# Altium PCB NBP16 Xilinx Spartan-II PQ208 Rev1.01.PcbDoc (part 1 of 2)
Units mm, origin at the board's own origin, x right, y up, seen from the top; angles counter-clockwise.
Board outline 69 x 80.99 mm, 2 copper layers (Top Layer, Bottom Layer); 48 components, 186 nets, 518 pads, 188 vias.
Unrouted connection lines stored in the file: 1.
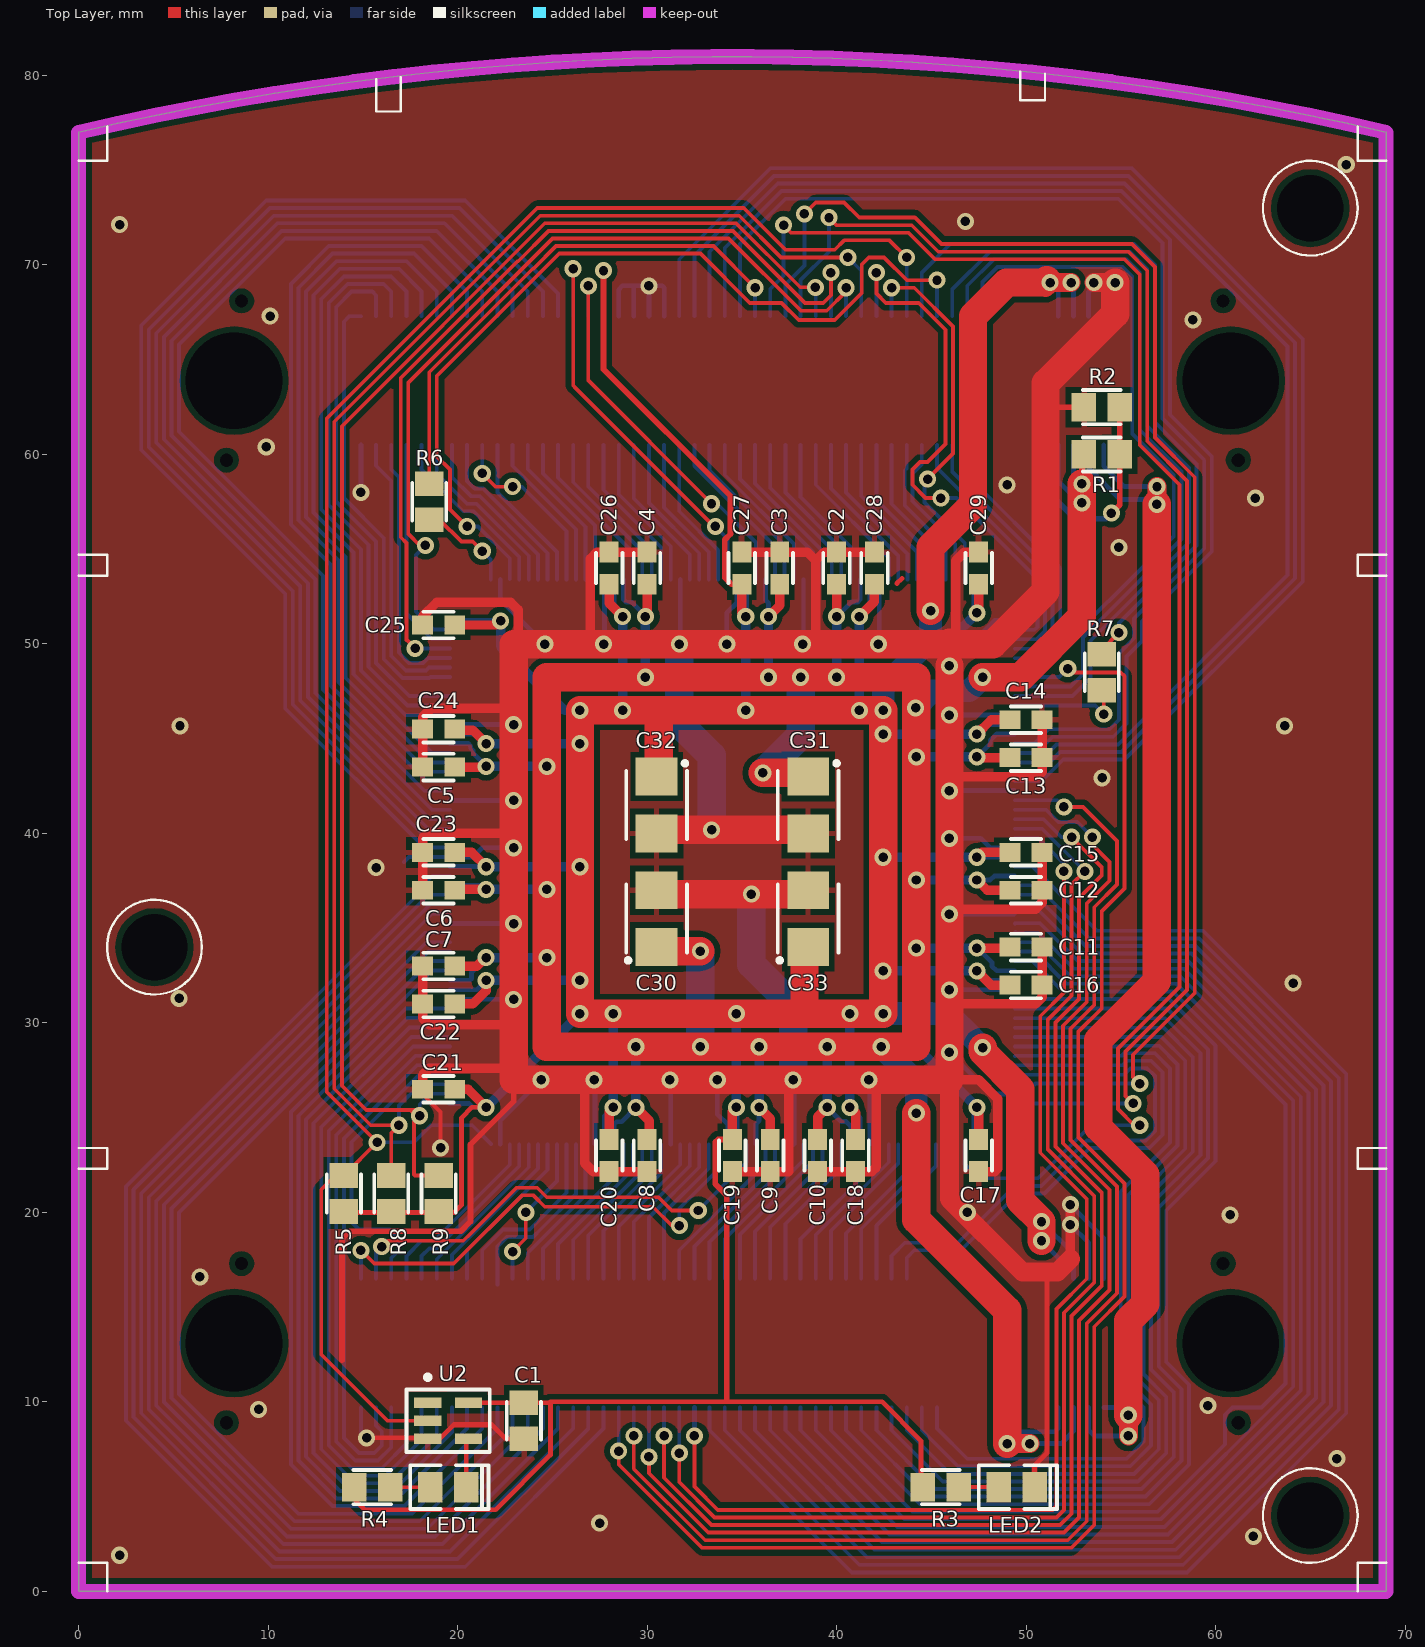
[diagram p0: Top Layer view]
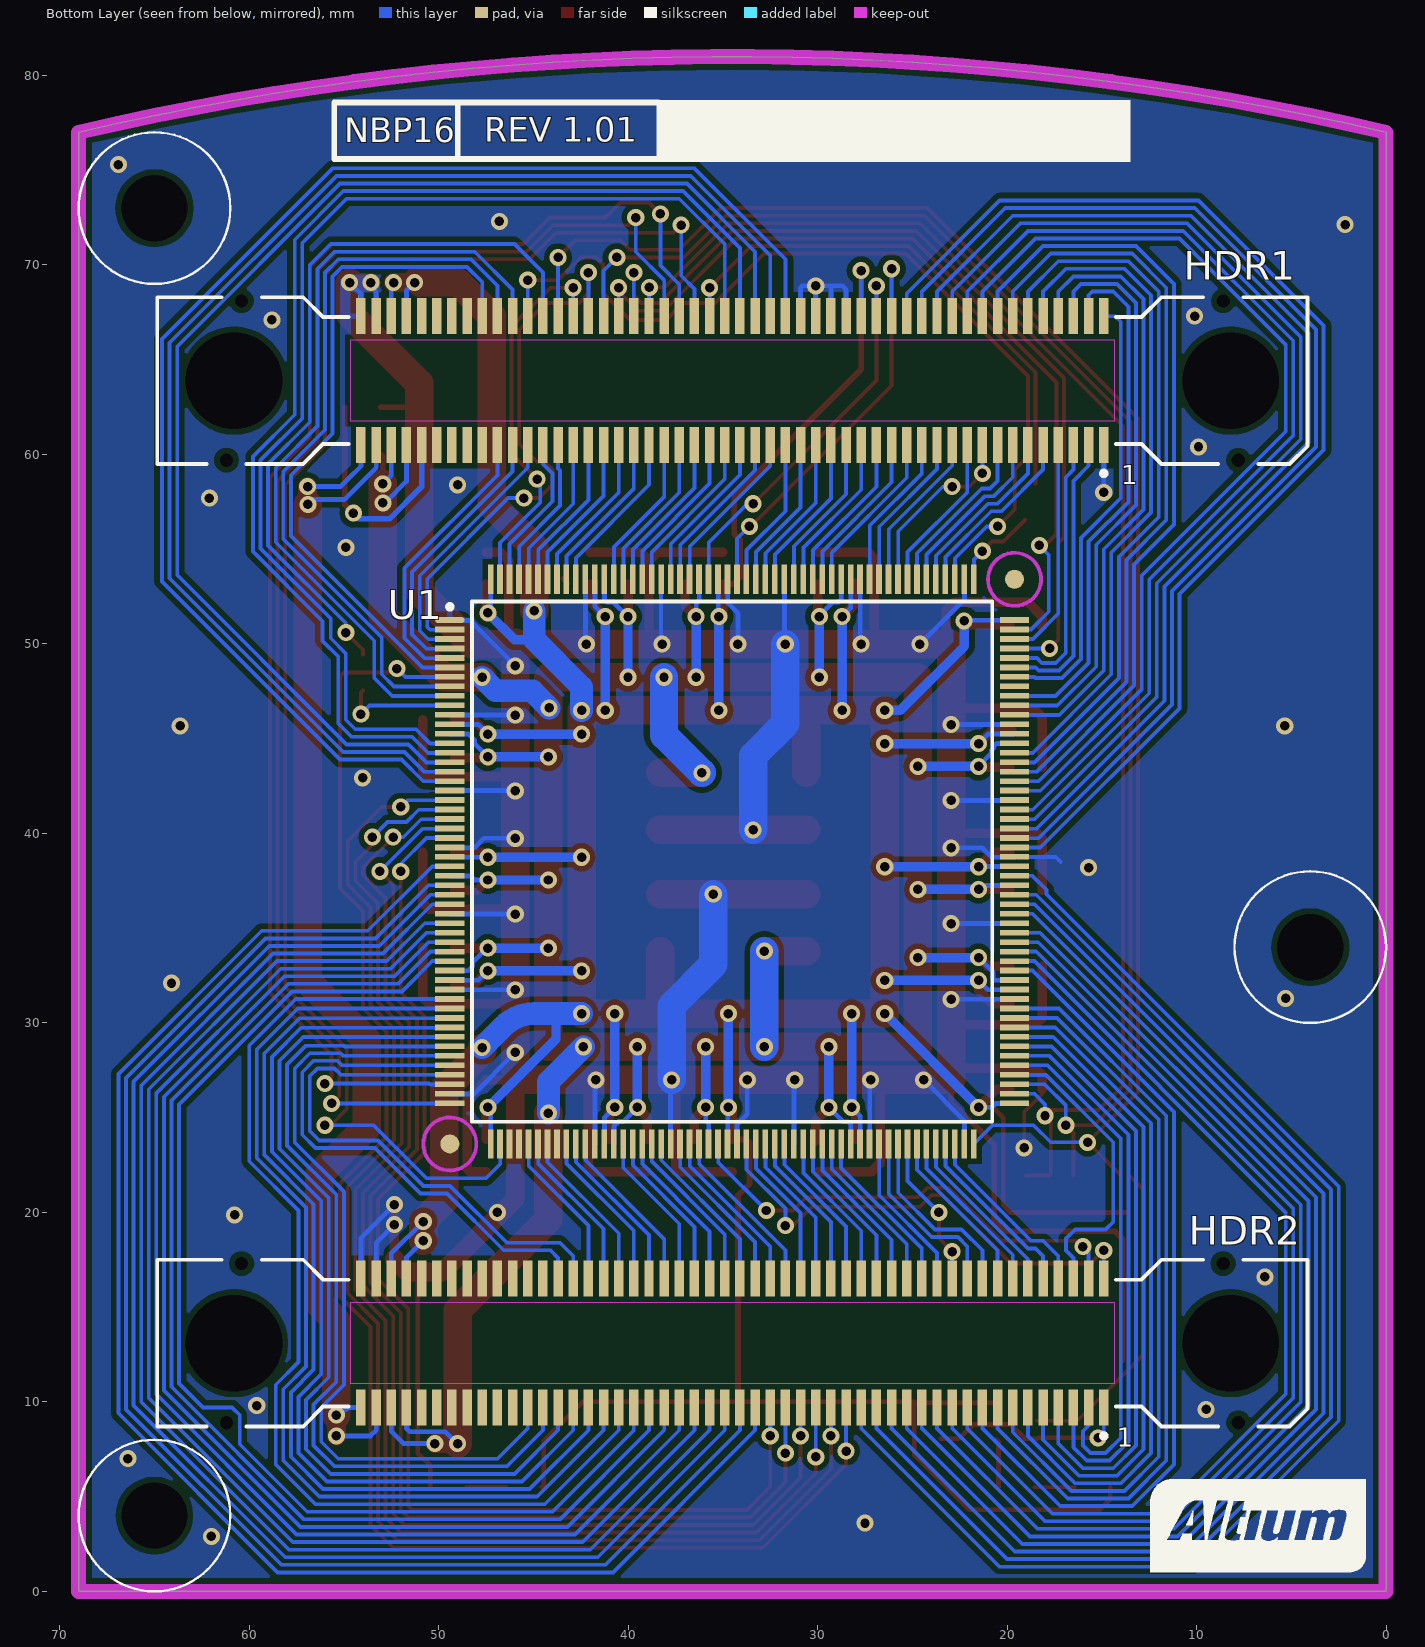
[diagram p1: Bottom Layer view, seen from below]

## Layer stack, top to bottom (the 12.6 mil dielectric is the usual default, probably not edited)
Top Layer: signal copper 0.0356
Dielectric: core 0.32, FR-4, Dk 4.8
Bottom Layer: signal copper 0.0356

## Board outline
0,0 0.001,77 cw(c34.5,-69.801) 69,77 69,0

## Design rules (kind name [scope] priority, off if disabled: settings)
Clearance Clearance_Polygons [InPolygon] p1: gap=0.3
Clearance [All] p2: gap=0.2
ComponentClearance [All] p1: gap=0.2 collisioncheckmode=3 verticalgap=0.254 showdistances=FALSE
FabricationTestPointUsage TestPointUsage [All] p1 off: valid=0 allowmultiple=FALSE
FabricationTestpoint Testpoint [All] p1 off: side=3 testpointundercomponent=TRUE minsize=1.016 maxsize=2.54 preferedsize=1.524 minholesize=0 maxholesize=1.016 preferedholesize=0.813 testpointgrid=0.025 allowsidetop=TRUE allowsidebottom=TRUE usegrid=TRUE gridtolerance=0
HoleSize [All] p1: absolutevalues=TRUE maxlimit=5.2 minlimit=0.25 maxpercent=80.000 minpercent=20.000
PlaneClearance [All] p1: clearance=0.5
PlaneConnect PlaneConnect_Vias [IsVia] p1: planeconnectstyle=Direct reliefexpansion=0.508 reliefentries=4 reliefconductorwidth=0.254 reliefairgap=0.254
PlaneConnect [All] p2: planeconnectstyle=Relief reliefexpansion=0.5 reliefentries=4 reliefconductorwidth=0.25 reliefairgap=0.25
PolygonConnect [All] p1: connectstyle=Relief reliefconductorwidth=0.3 reliefentries=4 polygonreliefangle="90 Angle"
RoomDefinition BOCD_SpartanII_PQ208 [InComponentClass('BOCD_SpartanII_PQ208')] p1 off: confinementstyle=ConfineIn formatcopy=TRUE lockcomponents=FALSE outline 3.7,3.8 65.3,3.8 65.3,68.8 3.7,68.8
RoutingVias [All] p1: holewidth=0.5 width=0.9 viastyle="Through Hole" minholewidth=0.3 minwidth=0.6 maxholewidth=0.5 maxwidth=0.9
SMDNeckDown [All] p1: percent=100.000
SilkscreenOverComponentPads [All] p1: minsilkscreentomaskgap=0.254
SolderMaskExpansion SolderMaskExpansion_Vias [IsVia] p1: expansion=-0.2
SolderMaskExpansion [All] p2: expansion=0.1
Width [All] p1: maxlimit=1.5 minlimit=0.2 preferedwidth=0.25
21 further rules are at their usual default settings.

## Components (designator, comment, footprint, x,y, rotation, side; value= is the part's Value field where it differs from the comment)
C1 "0.1uF" CC2012-0805 23.5,9 r90 top
C2 "0.1uF" CC1608-0603 40,54 r90 top
C3 "0.1uF" CC1608-0603 37,54 r90 top
C4 "0.1uF" CC1608-0603 30,54 r90 top
C5 "0.1uF" CC1608-0603 19,43.5 r180 top
C6 "0.1uF" CC1608-0603 19,37 r180 top
C7 "0.1uF" CC1608-0603 19,33 r180 top
C8 "0.1uF" CC1608-0603 30,23 r270 top
C9 "0.1uF" CC1608-0603 36.5,23 r270 top
C10 "0.1uF" CC1608-0603 39,23 r270 top
C11 "0.1uF" CC1608-0603 50,34 r0 top
C12 "0.1uF" CC1608-0603 50,37 r0 top
C13 "0.1uF" CC1608-0603 50,44 r0 top
C14 "0.1uF" CC1608-0603 50,46 r0 top
C15 "0.1uF" CC1608-0603 50,39 r0 top
C16 "0.1uF" CC1608-0603 50,32 r0 top
C17 "0.1uF" CC1608-0603 47.5,23 r90 top
C18 "0.1uF" CC1608-0603 41,23 r90 top
C19 "0.1uF" CC1608-0603 34.5,23 r90 top
C20 "0.1uF" CC1608-0603 28,23 r90 top
C21 "0.1uF" CC1608-0603 19,26.5 r0 top
C22 "0.1uF" CC1608-0603 19,31 r180 top
C23 "0.1uF" CC1608-0603 19,39 r180 top
C24 "0.1uF" CC1608-0603 19,45.5 r180 top
C25 "0.1uF" CC1608-0603 19,51 r0 top
C26 "0.1uF" CC1608-0603 28,54 r270 top
C27 "0.1uF" CC1608-0603 35,54 r270 top
C28 "0.1uF" CC1608-0603 42,54 r270 top
C29 "0.1uF" CC1608-0603 47.5,54 r270 top
C30 "10uF TANT" MCCT-B 30.5,35.5 r90 top
C31 "10uF TANT" MCCT-B 38.5,41.5 r270 top
C32 "10uF TANT" MCCT-B 30.5,41.5 r270 top
C33 "10uF TANT" MCCT-B 38.5,35.5 r90 top
HDR1 "54075-1009" 54075 34.5,63.9 r0 bottom locked
HDR2 "54075-1009" 54075 34.5,13.1 r0 bottom locked
LED1 "HSMG-C170" "SMD _LED" 19.5,5.5 r180 top locked
LED2 "HSMH-C170" "SMD _LED" 49.5,5.5 r180 top locked
R1 "82R 1%" CC2012-0805 54,60 r0 top
R2 "680R 1%" CC2012-0805 54,62.5 r180 top
R3 "270R" CC2012-0805 45.5,5.5 r0 top
R4 "270R" CC2012-0805 15.5,5.5 r180 top
R5 "4K7" CC2012-0805 14,21 r90 top
R6 "100R" CC2012-0805 18.5,57.5 r270 top
R7 "100R" CC2012-0805 54,48.5 r90 top
R8 "4K7" CC2012-0805 16.5,21 r90 top
R9 "4K7" CC2012-0805 19,21 r90 top
U1 "XC2S200-6PQ208C" F-QFP28X28-G208/P.5N 34.5,38.5 r180 bottom locked
U2 "SN74LVC1G04DBV" SO-G5/P.95 19.5,9 r270 top

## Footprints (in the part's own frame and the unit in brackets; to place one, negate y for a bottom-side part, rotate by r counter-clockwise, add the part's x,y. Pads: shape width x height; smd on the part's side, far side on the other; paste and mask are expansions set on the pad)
54075 [mm] "Connector; Docking Station, Receptacle; 100 Position; Vertical"
  rect 0.5x1.9 smd: 1(-19.6,3.4) 2(-19.6,-3.4) 3(-18.8,3.4) 4(-18.8,-3.4) 5(-18,3.4) 6(-18,-3.4) 7(-17.2,3.4) 8(-17.2,-3.4) 9(-16.4,3.4) 10(-16.4,-3.4) 11(-15.6,3.4) 12(-15.6,-3.4) 13(-14.8,3.4) 14(-14.8,-3.4) 15(-14,3.4) 16(-14,-3.4) 17(-13.2,3.4) 18(-13.2,-3.4) 19(-12.4,3.4) 20(-12.4,-3.4) 21(-11.6,3.4) 22(-11.6,-3.4) 23(-10.8,3.4) 24(-10.8,-3.4) 25(-10,3.4) 26(-10,-3.4) 27(-9.2,3.4) 28(-9.2,-3.4) 29(-8.4,3.4) 30(-8.4,-3.4) 31(-7.6,3.4) 32(-7.6,-3.4) 33(-6.8,3.4) 34(-6.8,-3.4) 35(-6,3.4) 36(-6,-3.4) 37(-5.2,3.4) 38(-5.2,-3.4) 39(-4.4,3.4) 40(-4.4,-3.4) 41(-3.6,3.4) 42(-3.6,-3.4) 43(-2.8,3.4) 44(-2.8,-3.4) 45(-2,3.4) 46(-2,-3.4) 47(-1.2,3.4) 48(-1.2,-3.4) 49(-0.4,3.4) 50(-0.4,-3.4) 51(0.4,3.4) 52(0.4,-3.4) 53(1.2,3.4) 54(1.2,-3.4) 55(2,3.4) 56(2,-3.4) 57(2.8,3.4) 58(2.8,-3.4) 59(3.6,3.4) 60(3.6,-3.4) 61(4.4,3.4) 62(4.4,-3.4) 63(5.2,3.4) 64(5.2,-3.4) 65(6,3.4) 66(6,-3.4) 67(6.8,3.4) 68(6.8,-3.4) 69(7.6,3.4) 70(7.6,-3.4) 71(8.4,3.4) 72(8.4,-3.4) 73(9.2,3.4) 74(9.2,-3.4) 75(10,3.4) 76(10,-3.4) 77(10.8,3.4) 78(10.8,-3.4) 79(11.6,3.4) 80(11.6,-3.4) 81(12.4,3.4) 82(12.4,-3.4) 83(13.2,3.4) 84(13.2,-3.4) 85(14,3.4) 86(14,-3.4) 87(14.8,3.4) 88(14.8,-3.4) 89(15.6,3.4) 90(15.6,-3.4) 91(16.4,3.4) 92(16.4,-3.4) 93(17.2,3.4) 94(17.2,-3.4) 95(18,3.4) 96(18,-3.4) 97(18.8,3.4) 98(18.8,-3.4) 99(19.6,3.4) 100(19.6,-3.4)
  round 0.5 hole 0.7 unplated: MH1(-26.7,4.2) MH2(-25.9,-4.2) MH3(26.7,4.2) MH4(25.9,-4.2)
  round 4.8 hole 5.1 unplated: MH5(-26.3,0) MH6(26.3,0)
  Top Layer keep-out region: -20.15,2.15 20.15,2.15 20.15,-2.15 -20.15,-2.15
  silkscreen extent -30.35,-4.4 30.35,5.02
CC1608-0603 [mm]
  rect 1.1x1 smd: 1(-0.85,0) 2(0.85,0)
  silkscreen extent -0.8,-0.7 0.8,0.7
CC2012-0805 [mm]
  rect 1.3x1.5 smd: 1(-0.95,0.003) 2(0.95,0.003)
  silkscreen extent -1,-0.9 1,0.9
F-QFP28X28-G208/P.5N [mm]
  oval 1.55x0.3 smd: 1(-14.91,12.761)
  rect 1.55x0.3 smd: 2(-14.91,12.261) 3(-14.91,11.761) 4(-14.91,11.261) 5(-14.91,10.761) 6(-14.91,10.261) 7(-14.91,9.761) 8(-14.91,9.261) 9(-14.91,8.761) 10(-14.91,8.261) 11(-14.91,7.761) 12(-14.91,7.261) 13(-14.91,6.761) 14(-14.91,6.261) 15(-14.91,5.761) 16(-14.91,5.261) 17(-14.91,4.761) 18(-14.91,4.261) 19(-14.91,3.761) 20(-14.91,3.261) 21(-14.91,2.761) 22(-14.91,2.261) 23(-14.91,1.761) 24(-14.91,1.261) 25(-14.91,0.761) 26(-14.91,0.261) 27(-14.91,-0.239) 28(-14.91,-0.739) 29(-14.91,-1.239) 30(-14.91,-1.739) 31(-14.91,-2.239) 32(-14.91,-2.739) 33(-14.91,-3.239) 34(-14.91,-3.739) 35(-14.91,-4.239) 36(-14.91,-4.739) 37(-14.91,-5.239) 38(-14.91,-5.739) 39(-14.91,-6.239) 40(-14.91,-6.739) 41(-14.91,-7.239) 42(-14.91,-7.739) 43(-14.91,-8.239) 44(-14.91,-8.739) 45(-14.91,-9.239) 46(-14.91,-9.739) 47(-14.91,-10.239) 48(-14.91,-10.739) 49(-14.91,-11.239) 50(-14.91,-11.739) 51(-14.91,-12.239) 52(-14.91,-12.739) 105(14.89,-12.739) 106(14.89,-12.239) 107(14.89,-11.739) 108(14.89,-11.239) 109(14.89,-10.739) 110(14.89,-10.239) 111(14.89,-9.739) 112(14.89,-9.239) 113(14.89,-8.739) 114(14.89,-8.239) 115(14.89,-7.739) 116(14.89,-7.239) 117(14.89,-6.739) 118(14.89,-6.239) 119(14.89,-5.739) 120(14.89,-5.239) 121(14.89,-4.739) 122(14.89,-4.239) 123(14.89,-3.739) 124(14.89,-3.239) 125(14.89,-2.739) 126(14.89,-2.239) 127(14.89,-1.739) 128(14.89,-1.239) 129(14.89,-0.739) 130(14.89,-0.239) 131(14.89,0.261) 132(14.89,0.761) 133(14.89,1.261) 134(14.89,1.761) 135(14.89,2.261) 136(14.89,2.761) 137(14.89,3.261) 138(14.89,3.761) 139(14.89,4.261) 140(14.89,4.761) 141(14.89,5.261) 142(14.89,5.761) 143(14.89,6.261) 144(14.89,6.761) 145(14.89,7.261) 146(14.89,7.761) 147(14.89,8.261) 148(14.89,8.761) 149(14.89,9.261) 150(14.89,9.761) 151(14.89,10.261) 152(14.89,10.761) 153(14.89,11.261) 154(14.89,11.761) 155(14.89,12.261) 156(14.89,12.761)
  rect 0.3x1.55 smd: 53(-12.76,-14.889) 54(-12.26,-14.889) 55(-11.76,-14.889) 56(-11.26,-14.889) 57(-10.76,-14.889) 58(-10.26,-14.889) 59(-9.76,-14.889) 60(-9.26,-14.889) 61(-8.76,-14.889) 62(-8.26,-14.889) 63(-7.76,-14.889) 64(-7.26,-14.889) 65(-6.76,-14.889) 66(-6.26,-14.889) 67(-5.76,-14.889) 68(-5.26,-14.889) 69(-4.76,-14.889) 70(-4.26,-14.889) 71(-3.76,-14.889) 72(-3.26,-14.889) 73(-2.76,-14.889) 74(-2.26,-14.889) 75(-1.76,-14.889) 76(-1.26,-14.889) 77(-0.76,-14.889) 78(-0.26,-14.889) 79(0.24,-14.889) 80(0.74,-14.889) 81(1.24,-14.889) 82(1.74,-14.889) 83(2.24,-14.889) 84(2.74,-14.889) 85(3.24,-14.889) 86(3.74,-14.889) 87(4.24,-14.889) 88(4.74,-14.889) 89(5.24,-14.889) 90(5.74,-14.889) 91(6.24,-14.889) 92(6.74,-14.889) 93(7.24,-14.889) 94(7.74,-14.889) 95(8.24,-14.889) 96(8.74,-14.889) 97(9.24,-14.889) 98(9.74,-14.889) 99(10.24,-14.889) 100(10.74,-14.889) 101(11.24,-14.889) 102(11.74,-14.889) 103(12.24,-14.889) 104(12.74,-14.889) 157(12.74,14.911) 158(12.24,14.911) 159(11.74,14.911) 160(11.24,14.911) 161(10.74,14.911) 162(10.24,14.911) 163(9.74,14.911) 164(9.24,14.911) 165(8.74,14.911) 166(8.24,14.911) 167(7.74,14.911) 168(7.24,14.911) 169(6.74,14.911) 170(6.24,14.911) 171(5.74,14.911) 172(5.24,14.911) 173(4.74,14.911) 174(4.24,14.911) 175(3.74,14.911) 176(3.24,14.911) 177(2.74,14.911) 178(2.24,14.911) 179(1.74,14.911) 180(1.24,14.911) 181(0.74,14.911) 182(0.24,14.911) 183(-0.26,14.911) 184(-0.76,14.911) 185(-1.26,14.911) 186(-1.76,14.911) 187(-2.26,14.911) 188(-2.76,14.911) 189(-3.26,14.911) 190(-3.76,14.911) 191(-4.26,14.911) 192(-4.76,14.911) 193(-5.26,14.911) 194(-5.76,14.911) 195(-6.26,14.911) 196(-6.76,14.911) 197(-7.26,14.911) 198(-7.76,14.911) 199(-8.26,14.911) 200(-8.76,14.911) 201(-9.26,14.911) 202(-9.76,14.911) 203(-10.26,14.911) 204(-10.76,14.911) 205(-11.26,14.911) 206(-11.76,14.911) 207(-12.26,14.911) 208(-12.76,14.911)
  round 1 smd mask+1: FID1(-14.91,-14.889) FID2(14.89,14.911)
  Top Layer keep-out circle w0.2: c14.89,14.911 r1.4
  Top Layer keep-out circle w0.2: c-14.91,-14.889 r1.4
  silkscreen extent -15.03,-13.71 13.72,13.74
MCCT-B [mm]
  rect 2x2.2 smd: 1(-1.5,0) 2(1.5,0)
  silkscreen extent -2.3,-1.6 1.8,1.6
"SMD _LED" [mm]
  rect 1.3x1.6 smd: 1(0.95,0) 2(-0.95,0)
  silkscreen extent -2.13,-1.15 2,1.15
SO-G5/P.95 [mm]
  rect 0.55x1.45 smd: 1(-0.95,-1.075) 2(0,-1.075) 3(0.95,-1.075) 4(0.95,1.075) 5(-0.95,1.075)
  silkscreen extent -2.42,-2.2 1.65,2.2

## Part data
C1 C2 C3 C4 C5 C6 C7 C8 C9 C10 C11 C12 C13 C14 C15 C16 C17 C18 C19 C20 C21 C22 C23 C24 C25 C26 C27 C28 C29: library part CAP, "Capacitor"
C30 C31 C32 C33: library part CAP_POLAR, "Polar Capacitor"
HDR1 HDR2: "Board-to-Board, Docking Station, 0.80mm (.031\") Pitch, Shielded Receptacle, Vertical, Ultra Low Profile, SMT"
LED1 LED2: library part HSMX-C670, "Typical RED GaAs SMD LED Agilent make"
R1 R2 R3 R4 R5 R6 R7 R8 R9: library part RES, "Resistor"
U1: "Spartan-II 2.5V FPGA, 208-Pin PQFP, Higher Performance, Commercial Grade"
U2: library part SN74AHC1G04DBVR

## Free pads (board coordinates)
  round 3.2 hole 3.5 unplated: LP(4,34) LP(65,4) LP(65,73)

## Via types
v1: diameter 0.9, hole 0.5, Top Layer to Bottom Layer, tented both sides, 188 vias

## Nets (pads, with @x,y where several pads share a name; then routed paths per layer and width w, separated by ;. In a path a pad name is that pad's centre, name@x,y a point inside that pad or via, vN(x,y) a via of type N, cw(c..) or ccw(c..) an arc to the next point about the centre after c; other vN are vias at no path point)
5V: HDR1.97 HDR1.99 HDR2.97 HDR2.99 | length 67.6
  Top Layer w1: v1(55.4,8.2) v1(55.4,9.3) ; v1(56.9,57.364) v1(56.911,58.304)
  Top Layer w1.5: v1(55.4,9.3) 55.4,13.538 55.4,14.284 56.3,15.184 56.3,22 53.8,24.5 53.8,29.087 55.05,30.337 56.9,32.187 v1(56.9,57.364)
  Bottom Layer w0.25: HDR2.97@53.3,9.7 53.3,8.5 53.6,8.2 v1(55.4,8.2) ; HDR1.97@53.3,60.5 53.3,59.3 54.982,57.618 56.646,57.618 v1(56.9,57.364) ; HDR2.99@54.1,9.7 54.7,9.7 v1(55.4,9.3) ; HDR1.99@54.1,60.5 54.1,59.375 54.77,58.718 55.184,58.304 v1(56.911,58.304)
AUDIO_SPI_CSN: HDR1.11 U1.161 | length 9.4
  Bottom Layer w0.2: HDR1.11@18.9,60.5 18.9,59 20.5,57.4 21.003,57.4 23.75,54.653 U1.161@23.75,53.4
BLUE0: HDR1.14 U1.140 | length 40.5
  Bottom Layer w0.2: U1.140@19.6,43.25 18.45,43.25 13.7,48 13.7,54.434 11.6,56.534 11.6,68.8 13.4,70.6 17.7,70.6 19.7,68.6 HDR1.14@19.7,67.3
BLUE1: HDR1.16 U1.139 | length 42.9
  Bottom Layer w0.2: U1.139@19.6,42.75 18.35,42.75 13.3,47.8 13.3,54.2 11.2,56.3 11.2,69 13.2,71 18.1,71 20.5,68.6 HDR1.16@20.5,67.3
BOC_CTS: HDR1.13 U1.162 | length 9.3
  Bottom Layer w0.2: HDR1.13@19.7,60.5 19.7,58.8 20.7,57.8 21.169,57.8 24.25,54.719 U1.162@24.25,53.4
BOC_RTS: HDR1.17 U1.165 | length 9.8
  Top Layer w0.2: v1(21.3,59) 22,58.3 v1(22.9,58.3)
  Bottom Layer w0.2: v1(21.3,59) HDR1.17@21.3,60.5 ; v1(22.9,58.3) 23.4,58.3 25.75,55.95 U1.165@25.75,53.4
BOC_RX: HDR1.19 U1.164 | length 8.4
  Bottom Layer w0.2: HDR1.19@22.1,60.5 22.1,58 25.25,54.85 U1.164@25.25,53.4
BOC_TX: HDR1.15 U1.163 | length 9.1
  Bottom Layer w0.2: HDR1.15@20.5,60.5 20.5,58.6 20.9,58.2 21.334,58.2 24.75,54.784 U1.163@24.75,53.4
BUZZER: HDR2.24 U1.94 | length 8.4
  Bottom Layer w0.2: HDR2.24@23.7,16.5 23.7,17.857 26.75,20.907 U1.94@26.75,23.6
CAN_RXD: HDR1.4 U1.148 | length 27.9
  Bottom Layer w0.2: HDR1.4@15.7,67.3 15.7,68.4 15.5,68.6 14.4,68.6 13.6,67.8 13.6,57.5 15.7,55.4 15.7,49 17.45,47.25 U1.148@19.6,47.25
CAN_TXD: HDR1.2 U1.150 | length 23.6
  Bottom Layer w0.2: HDR1.2@14.9,67.3 14.3,67.3 14,67 14,57.7 16.1,55.6 16.1,49.2 17.1,48.2 18.5,48.2 18.561,48.261 U1.150@19.61,48.261
FPGA_AUX0: HDR1.86
FPGA_AUX1: HDR1.88
FPGA_AUX2: HDR1.90
FPGA_AUX3: HDR1.92
FPGA_CCLK: HDR1.66 U1.155 | length 45
  Top Layer w0.2: v1(18.3,55.2) 18,55.2 17.4,55.8 17.4,63.8 25,71.4 34.3,71.4 38.119,67.581 39.481,67.581 40.5,68.6 v1(40.5,68.8)
  Bottom Layer w0.2: v1(18.3,55.2) 17.8,54.7 17.8,51.7 18.739,50.761 U1.155@19.61,50.761 ; HDR1.66@40.5,67.3 v1(40.5,68.8)
FPGA_CLK: HDR2.2 U1.80 | length 25.9
  Top Layer w0.2: v1(14.9,18) 15.6,17.3 19.8,17.3 23.4,20.9 24,20.9 24.6,20.3 30.3,20.3 31.3,19.3 v1(31.7,19.3)
  Bottom Layer w0.2: HDR2.2@14.9,16.5 v1(14.9,18) ; v1(31.7,19.3) 31.7,20.2 33.75,22.25 U1.80@33.75,23.6
FPGA_CLK_1: HDR1.30 U1.182 | length 21.9
  Top Layer w0.2: v1@26.1,69.6 26.1,63.634 26.22,63.514 33.534,56.2 v1(33.6,56.2)
  Bottom Layer w0.2: HDR1.30@26.1,67.3 v1@26.1,69.6 ; v1(33.6,56.2) 34.25,55.55 U1.182@34.25,53.4
  other v1: 26.1,69.8
FPGA_CLK_2: HDR1.32 U1.185 | length 20.5
  Top Layer w0.2: v1@26.9,68.7 26.9,63.9 v1(33.4,57.4)
  Bottom Layer w0.2: HDR1.32@26.9,67.3 v1@26.9,68.7 ; v1(33.4,57.4) 33.7,57.4 35.75,55.35 U1.185@35.75,53.4
  other v1: 26.9,68.9
FPGA_DIN: HDR1.64 U1.153 | length 47.6
  Top Layer w0.2: v1(17.761,49.761) 17.323,50.2 17.3,50.2 17.3,55.334 17,55.634 17,64.034 23.166,70.2 23.2,70.2 24.8,71.8 34.534,71.8 38.334,68 39.3,68 39.7,68.4 v1(39.7,69.6)
  Bottom Layer w0.2: v1(17.761,49.761) U1.153@19.61,49.761 ; HDR1.64@39.7,67.3 v1(39.7,69.6)
FPGA_DONE: HDR1.74 R5.2 U1.104 U2.2 | length 105.2
  Top Layer w0.2: R5.2@13.55,21.95 12.8,21.2 12.8,12.5 16.3,9 U2.2@18.425,9 ; R5.2@13.997,21.95 v1(15.748,23.7) 13.092,26.356 13.092,61.892 24.2,73 35.1,73 37.3,70.8 39.9,70.8 40.4,71.3 42.8,71.3 v1(43.7,70.4)
  Bottom Layer w0.2: v1(15.748,23.7) 17.7,23.7 18.6,24.6 20.771,24.6 U1.104@21.76,23.611 ; HDR1.74@43.7,67.3 v1(43.7,70.4)
FPGA_INIT: HDR1.68 R8.2 U1.107 | length 82.4
  Top Layer w0.2: R8.2@16.497,21.95 16.497,24.197 v1(16.9,24.6) 15.413,24.6 13.492,26.522 13.492,61.726 24.366,72.6 34.866,72.6 37.066,70.4 v1(40.6,70.4)
  Bottom Layer w0.2: v1(16.9,24.6) 16.9,25.634 18.027,26.761 U1.107@19.61,26.761 ; v1(40.6,70.4) 41.3,69.7 HDR1.68@41.3,67.3
FPGA_M0: HDR1.60 U1.52 | length 76.4
  Top Layer w0.2: v1(39.6,72.5) 40,72.1 43.966,72.1 45.366,70.7 55.4,70.7 56.4,69.7 56.4,60.7 58.5,58.6 58.5,31.736 55.25,28.486 55.25,26.15 v1(55.65,25.75)
  Bottom Layer w0.2: HDR1.60@38.1,67.3 38.1,69.2 39.6,70.7 v1(39.6,72.5) ; U1.52@49.4,25.75 v1(55.65,25.75)
FPGA_M1: HDR1.58 U1.50 | length 78.1
  Top Layer w0.2: v1(38.3,72.7) 38.9,73.3 40.4,73.3 41.2,72.5 44.131,72.5 45.531,71.1 55.6,71.1 56.8,69.9 56.8,60.9 58.9,58.8 58.9,31.57 55.65,28.32 55.65,27.15 v1(56,26.8)
  Bottom Layer w0.2: HDR1.58@37.3,67.3 37.3,68.966 38.3,69.966 v1(38.3,72.7) ; U1.50@49.4,26.75 50.45,26.75 50.5,26.8 v1(56,26.8)
FPGA_M2: HDR1.56 U1.54 | length 84.5
  Top Layer w0.2: v1(37.2,72.1) 37.6,71.7 43.8,71.7 45.2,70.3 55.2,70.3 56,69.5 56,60.5 58.1,58.4 58.1,31.902 54.85,28.652 54.85,25.45 55.7,24.6 v1(56,24.6)
  Bottom Layer w0.2: HDR1.56@36.5,67.3 36.5,68.731 37.2,69.431 v1(37.2,72.1) ; U1.54@46.75,23.6 46.75,22.55 47.5,21.8 50.634,21.8 53.434,24.6 v1(56,24.6)
FPGA_PROGRAM: HDR1.62 R9.2 U1.106 | length 79.3
  Top Layer w0.2: 17.5,25.4 17.9,25 17.7,24.8 17.7,22 17.75,21.95 R9.2@18.997,21.95 ; v1(18,25.1) 17.7,25.4 15.179,25.4 13.892,26.687 13.892,61.492 24.6,72.2 34.7,72.2 38.079,68.821 v1(38.879,68.821)
  Bottom Layer w0.2: v1(18,25.1) 18,25.7 18.561,26.261 U1.106@19.61,26.261 ; HDR1.62@38.9,67.3 v1@38.9,68.8
FPGA_TCK: HDR1.72 U1.207 | length 20.5
  Top Layer w0.2: v1(42.9,68.8) 44.1,68.8 46.15,66.75 46.15,60.05 v1(44.8,58.7)
  Bottom Layer w0.2: HDR1.72@42.9,67.3 v1(42.9,68.8) ; v1(44.8,58.7) 44.636,58.536 44.636,57.464 46.76,55.34 U1.207@46.76,53.411 ; U1.207@46.75,53.4 U1.207@46.75,53.411
FPGA_TDI: HDR1.78 U1.159 | length 47.8
  Top Layer w0.2: v1(20.5,56.2) 19.6,57.1 19.6,59.2 18.903,59.897 18.903,64.137 25.366,70.6 32.818,70.6 35.418,68 37.1,68 38,67.1 39.9,67.1 41.328,68.528 41.328,70.028 41.7,70.4 42.5,70.4 43.7,69.2 v1(45.3,69.2)
  Bottom Layer w0.2: v1(20.5,56.2) 21.072,56.2 22.75,54.522 U1.159@22.75,53.411 ; HDR1.78@45.3,67.3 v1(45.3,69.2)
FPGA_TDO: HDR1.54 R6.1 | length 28.3
  Top Layer w0.2: R6.1@18.503,58.45 18.503,64.337 23.966,69.8 24,69.8 25.2,71 33.5,71 v1(35.7,68.8)
  Bottom Layer w0.2: HDR1.54@35.7,67.3 v1(35.7,68.8)
FPGA_TDO#: R6.2 U1.157 | length 4.6
  Top Layer w0.2: R6.2@19.05,56.55 20.2,55.4 20.8,55.4 v1(21.3,54.9)
  Bottom Layer w0.2: v1(21.3,54.9) 21.75,54.45 U1.157@21.75,53.4
FPGA_TMS: HDR1.70 U1.2 | length 29.4
  Top Layer w0.2: v1(42.1,69.6) 42.1,68.5 42.6,68 44.334,68 45.75,66.584 45.75,60.55 44.8,59.6 44.4,59.6 44,59.2 44,58.4 44.7,57.7 v1(45.5,57.7)
  Bottom Layer w0.2: HDR1.70@42.1,67.3 v1(42.1,69.6) ; v1(45.5,57.7) 46.334,57.7 50.6,53.434 50.6,50.9 50.45,50.75 U1.2@49.4,50.75
GND: C1.1 C2.2 C3.2 C4.2 C5.2 C6.2 C7.2 C8.2 C9.2 C10.2 C11.2 C12.2 C13.2 C14.2 C15.2 C16.2 C17.1 C18.1 C19.1 C20.1 C21.1 C22.2 C23.2 C24.2 C25.1 C26.1 C27.1 C28.1 C29.1 C30.2 C31.2 C32.2 C33.2 HDR1.1 HDR1.36 HDR1.38 HDR1.40 HDR1.42 HDR1.98 HDR1.100 HDR2.1 HDR2.98 HDR2.100 LED2.2 R2.2 U1.1 U1.11 U1.19 U1.25 U1.32 U1.40 U1.51 U1.64 U1.72 U1.79 U1.85 U1.93 U1.103 U1.116 U1.124 U1.131 U1.137 U1.145 U1.158 U1.169 U1.177 U1.183 U1.190 U1.198 U2.3 | length 448.2
  Top Layer w0.2: C21.1@18.15,26.5 18.15,26.25 19.1,25.3 v1(19.1,23.4)
  Top Layer w0.25: v1(15.2,8.1) U2.3@18.375,8.1 ; U2.3@18.425,8.05 19.05,8.05 19.8,8.8 21.8,8.8 22.55,8.05 C1.1@23.497,8.05 ; LED2.2@50.45,5.5 50.45,6.65 51.1,7.3 51.1,16.85
  Top Layer w0.3: 13.9,12.2 13.9,18.6 14.3,19 20.164,19 20.683,19.519 20.683,23.583 22.958,25.858 22.958,26.992 ; 51.028,62.497 R2.2@53.05,62.497
  Top Layer w0.5: C21.1@18.15,26.5 18.15,27.25 18.5,27.6 22.958,27.6 ; C7.2@18.15,33 C22.2@18.15,31 18.15,30.25 18.5,29.9 22.858,29.9 22.958,30 ; C6.2@18.15,37 C23.2@18.15,39 18.15,39.75 18.4,40 22.7,40 ; C5.2@18.15,43.5 C24.2@18.15,45.5 18.15,46.15 18.6,46.6 22.858,46.6 ; C25.1@18.2,50.95 C25.1@18.15,51 18.15,51.45 18.9,52.2 22.8,52.2 23.2,51.8 23.2,49.992 ; 26.7,26.992 26.7,22.6 27.15,22.15 C20.1@28,22.15 C8.2@30,22.15 ; 27,49.992 27,54.5 27.35,54.85 C26.1@28,54.85 C4.2@30,54.85 ; C19.1@34.5,22.15 C9.2@36.5,22.15 37.45,22.15 37.48,22.18 v1@37.48,26.912 ; C27.1@35,54.85 38.45,54.85 38.9,54.4 ; v1@37.48,26.764 v1(37.708,26.992) ; 38.9,50.092 38.9,54.4 ; C10.2@39,22.15 C18.1@41,22.15 41.85,22.15 42.1,22.4 v1@42.1,26.992 ; C28.1@42,54.85 C2.2@40,54.85 39.35,54.85 38.9,54.4 ; 45.958,26.992 47.508,26.992 48.5,26 48.5,22.3 48.35,22.15 C17.1@47.5,22.15 ; 45.958,31 50.5,31 50.85,31.35 C16.2@50.85,32 C11.2@50.85,34 ; 45.958,43.1 46.058,43 50.6,43 50.85,43.25 C13.2@50.85,44 C14.2@50.85,46 ; v1@46.2,36.1 46.3,36 50.5,36 50.85,36.35 C12.2@50.85,37 C15.2@50.85,39 ; 46.3,50.2 46.3,54.4 46.75,54.85 C29.1@47.5,54.85 ; 52.339,17.537 v1(52.339,20.407) ; v1@54.01,42.942 v1(54.015,42.937)
  Top Layer w1: 45.958,26.992 45.958,20.707 49.815,16.85 51.652,16.85 52.339,17.537 ; v1(53.575,69.075) v1(54.7,69.075)
  Top Layer w1.5: C30.2@30.608,36.792 C33.2@38.308,36.792 ; C32.2@30.608,40.192 C31.2@38.308,40.192 ; 45.892,49.992 v1(42.208,49.992) v1(24.602,49.992) 22.958,49.992 22.958,26.992 45.958,26.992 v1(45.958,48.842) ; 45.958,50.058 45.958,49.992 48.25,49.992 51.025,52.767 51.025,63.75 54.701,67.418 v1(54.7,69.075)
  Bottom Layer w0.2: HDR2.1@14.9,9.7 14.9,8.4 v1(15.2,8.1) ; 17.172,38.497 17.437,38.761 U1.131@19.61,38.761 ; v1(38.208,49.992) 38.26,50.044 U1.190@38.26,53.411
  Bottom Layer w0.25: v1(14.9,58) HDR1.1@14.9,60.5 ; U1.124@19.558,35.242 v1(22.958,35.242) ; U1.131@19.558,38.742 20.808,38.742 21.308,39.242 v1(22.958,39.242) ; U1.137@19.558,41.742 v1(22.958,41.742) ; U1.145@19.6,45.75 v1@22.95,45.75 ; U1.116@19.608,31.242 19.6,31.25 22.95,31.25 v1(22.958,31.242) ; U1.103@22.25,23.6 22.25,24.834 v1(24.408,26.992) ; U1.158@22.25,53.4 22.25,52.345 v1(24.602,49.992) ; v1(27.208,26.992) 27.25,26.95 U1.93@27.25,23.6 ; v1(27.708,49.992) 27.75,50.034 U1.169@27.75,53.4 ; HDR1.36@28.5,67.3 28.5,68.7 28.7,68.9 v1(30.1,68.9) ; HDR1.38@29.3,67.3 29.3,68.9 ; HDR1.40@30.1,67.3 v1(30.1,68.9) ; HDR1.42@30.9,67.3 30.9,68.8 30.8,68.9 v1(30.1,68.9) ; v1(31.208,26.992) 31.25,26.95 U1.85@31.25,23.6 ; v1(31.708,49.992) 31.75,50.034 U1.177@31.75,53.4 ; v1(33.708,26.992) 33.708,25.192 34.25,24.65 U1.79@34.25,23.6 ; v1(34.208,49.992) 34.208,51.642 ; 34.708,52.142 34.208,51.642 ; U1.183@34.75,53.4 34.75,52.184 34.208,51.642 ; v1(37.708,26.992) 37.76,26.941 U1.72@37.76,23.611 ; v1(41.708,26.992) 41.75,26.95 U1.64@41.75,23.6 ; v1(42.208,49.992) 42.25,50.034 U1.198@42.25,53.4 ; v1(45.958,28.442) 48.158,26.242 U1.51@49.358,26.242 ; v1(45.958,35.742) U1.32@49.358,35.742 ; v1(45.958,39.742) 47.608,39.742 48.1,39.25 U1.25@49.4,39.25 ; v1(45.958,42.242) 45.977,42.261 U1.19@49.41,42.261 ; v1(45.958,46.242) 45.966,46.25 U1.11@49.4,46.25 ; v1(45.958,48.842) 48.278,51.163 48.358,51.242 U1.1@49.358,51.242 ; v1@45.966,31.75 U1.40@49.4,31.75 ; v1(52.339,19.357) 53.3,18.396 HDR2.98@53.3,16.5 ; v1(52.339,20.407) 54.1,18.646 HDR2.100@54.1,16.5 ; HDR1.98@53.3,67.3 53.3,68.575 53.687,68.962 53.75,69.025 v1(53.575,69.075) ; HDR1.100@54.1,67.3 54.1,68.475 v1(54.7,69.075)
  Bottom Layer w1.5: v1(31.708,49.992) 31.708,45.792 33.408,44.092 v1(33.408,40.192) ; v1(35.508,36.792) 35.508,33.092 37.708,30.892 v1(37.708,26.992)
  other v1: 2.159,1.905 62,2.9 27.5,3.6 66.4,7 9.5,9.6 59.6,9.8 6.4,16.6 60.774,19.873 46.9,20 5.3,31.3 45.958,31.742 64.1,32.1 15.7,38.2 5.349,45.68 63.642,45.68 22.958,45.742 54.9,55.1 62.1,57.7 49,58.4 9.9,60.4 58.8,67.1 10.1,67.3 2.159,72.136 46.8,72.3 66.9,75.3
GREEN0: HDR1.10 U1.142 | length 35.8
  Bottom Layer w0.2: HDR1.10@18.1,67.3 18.1,68.6 16.9,69.8 13.8,69.8 12.4,68.4 12.4,56.934 14.5,54.834 14.5,48.4 18.65,44.25 U1.142@19.6,44.25
GREEN1: HDR1.12 U1.141 | length 38.1
  Bottom Layer w0.2: HDR1.12@18.9,67.3 18.9,68.6 17.3,70.2 13.6,70.2 12,68.6 12,56.7 14.1,54.6 14.1,48.2 18.55,43.75 U1.141@19.6,43.75
HDRIVE: HDR1.18 U1.138 | length 51
  Bottom Layer w0.2: U1.138@19.6,42.25 18.25,42.25 12.9,47.6 12.9,53.6 5.3,61.2 5.3,65.8 10.9,71.4 18.5,71.4 21.3,68.6 HDR1.18@21.3,67.3
IO0: HDR2.7 U1.111 | length 31.9
  Bottom Layer w0.2: HDR2.7@17.3,9.7 17.3,7.8 16,6.5 14.4,6.5 13.2,7.7 13.2,24.3 17.661,28.761 U1.111@19.61,28.761
IO1: HDR2.9 U1.112 | length 34.1
  Bottom Layer w0.2: HDR2.9@18.1,9.7 18.1,8 16.2,6.1 14.2,6.1 12.8,7.5 12.8,24.5 17.561,29.261 U1.112@19.61,29.261
IO2: HDR2.11 U1.113 | length 36.4
  Bottom Layer w0.2: HDR2.11@18.9,9.7 18.9,8.2 16.4,5.7 14,5.7 12.4,7.3 12.4,24.7 17.461,29.761 U1.113@19.61,29.761
IO3: HDR2.13 U1.114 | length 38.7
  Bottom Layer w0.2: U1.114@19.61,30.261 17.361,30.261 12,24.9 12,7.1 13.8,5.3 16.6,5.3 19.7,8.4 HDR2.13@19.7,9.7
IO4: HDR2.15 U1.115 | length 40.9
  Bottom Layer w0.2: U1.115@19.61,30.761 17.261,30.761 11.6,25.1 11.6,6.9 13.6,4.9 16.8,4.9 20.5,8.6 HDR2.15@20.5,9.7
IO5: HDR2.17 U1.119 | length 43.9
  Bottom Layer w0.2: U1.119@19.61,32.761 18.661,32.761 11.2,25.3 11.2,6.7 13.4,4.5 17.2,4.5 21.3,8.6 HDR2.17@21.3,9.7
IO6: HDR2.19 U1.120 | length 51.8
  Bottom Layer w0.2: U1.120@19.61,33.261 18.561,33.261 5.3,20 5.3,10.4 11.6,4.1 17.6,4.1 22.1,8.6 HDR2.19@22.1,9.7
IO7: HDR2.21 U1.121 | length 54.1
  Bottom Layer w0.2: U1.121@19.61,33.761 18.461,33.761 4.9,20.2 4.9,10.2 11.4,3.7 18,3.7 22.9,8.6 HDR2.21@22.9,9.7
IO8: HDR2.23 U1.122 | length 56.5
  Bottom Layer w0.2: U1.122@19.61,34.261 18.361,34.261 4.5,20.4 4.5,10 11.2,3.3 18.4,3.3 23.7,8.6 HDR2.23@23.7,9.7
IO9: HDR2.25 U1.123 | length 58.9
  Bottom Layer w0.2: U1.123@19.61,34.761 18.261,34.761 4.1,20.6 4.1,9.8 11,2.9 18.8,2.9 24.5,8.6 HDR2.25@24.5,9.7
IO10: HDR2.27 U1.125 | length 61.5
  Bottom Layer w0.2: U1.125@19.61,35.761 18.661,35.761 3.7,20.8 3.7,9.6 10.8,2.5 19.2,2.5 25.3,8.6 HDR2.27@25.3,9.7
IO11: HDR2.29 U1.126 | length 63.8
  Bottom Layer w0.2: U1.126@19.61,36.261 18.561,36.261 3.3,21 3.3,9.4 10.6,2.1 19.6,2.1 26.1,8.6 HDR2.29@26.1,9.7
IO12: HDR2.31 U1.127 | length 66.2
  Bottom Layer w0.2: U1.127@19.61,36.761 18.461,36.761 2.9,21.2 2.9,9.2 10.4,1.7 20,1.7 26.9,8.6 HDR2.31@26.9,9.7
IO13: HDR2.33 U1.129 | length 68.9
  Bottom Layer w0.2: U1.129@19.61,37.761 18.661,37.761 17.923,37.023 17.923,36.789 2.5,21.366 2.5,9 10.2,1.3 20.4,1.3 27.7,8.6 HDR2.33@27.7,9.7
IO14: HDR2.35 U1.7 | length 84.1
  Top Layer w0.2: v1(28.5,7.4) 28.5,6.7 32.9,2.3 52.4,2.3 53.6,3.5 53.6,13.969 55.2,15.569 55.2,21.528 52.75,23.978 52.75,29.522 54,30.772 54,35.9 55.2,37.1 55.2,48.3 55,48.5 52.4,48.5 v1(52.2,48.7)
  Bottom Layer w0.2: v1(28.5,7.4) HDR2.35@28.5,9.7 ; U1.7@49.4,48.25 51.75,48.25 v1(52.2,48.7)
IO15: HDR2.37 U1.20 | length 74
  Top Layer w0.2: v1(29.3,8.2) 29.3,6.466 33.066,2.7 52.2,2.7 53.2,3.7 53.2,14.134 54.8,15.734 54.8,21.363 52.35,23.813 52.35,29.687 53.6,30.937 53.6,36.1 54.8,37.3 54.8,39.6 53,41.4 v1(52,41.4)
  Bottom Layer w0.2: v1(29.3,8.2) HDR2.37@29.3,9.7 ; U1.20@49.4,41.75 51.65,41.75 v1(52,41.4)
IO16: HDR2.39 U1.21 | length 71.5
  Top Layer w0.2: v1(30.1,7.1) 30.1,6.231 33.231,3.1 52,3.1 52.8,3.9 52.8,14.3 54.4,15.9 54.4,21.197 51.95,23.647 51.95,29.853 53.2,31.103 53.2,36.3 54.4,37.5 54.4,38.5 53.5,39.4 v1(53.5,39.8) ; v1@30.2,7.1 v1@30.2,7.3
  Bottom Layer w0.2: HDR2.39@30.1,9.7 30.1,7.4 v1@30.2,7.3 ; U1.21@49.4,41.25 51.05,41.25 51.7,40.6 52.7,40.6 v1(53.5,39.8)
IO17: HDR2.41 U1.22 | length 68.9
  Top Layer w0.2: v1(30.9,8.2) 30.9,5.997 33.397,3.5 51.8,3.5 52.4,4.1 52.4,14.534 54,16.134 54,21.031 51.55,23.481 51.55,30.019 52.8,31.269 52.8,36.6 54,37.8 54,38.2 v1(52.4,39.8)
  Bottom Layer w0.2: v1(30.9,8.2) HDR2.41@30.9,9.7 ; U1.22@49.4,40.75 50.916,40.75 51.866,39.8 v1(52.4,39.8)
IO18: HDR2.43 U1.23 | length 66
  Top Layer w0.2: v1(31.7,7.3) 31.7,5.763 33.563,3.9 51.6,3.9 52,4.3 52,14.7 53.6,16.3 53.6,20.866 51.15,23.316 51.15,30.184 52.4,31.434 52.4,37.3 v1(53.1,38)
  Bottom Layer w0.2: v1(31.7,7.3) HDR2.43@31.7,9.7 ; U1.23@49.4,40.25 50.85,40.25 v1(53.1,38)
IO19: HDR2.45 U1.24 | length 63.1
  Top Layer w0.2: v1(32.5,8.2) 32.5,5.528 33.728,4.3 51.4,4.3 51.6,4.5 51.6,14.9 53.2,16.5 53.2,20.7 50.75,23.15 50.75,30.35 52,31.6 v1(52,38)
  Bottom Layer w0.2: U1.24@49.4,39.75 U1.24@49.41,39.75 ; U1.24@49.41,39.761 50.639,39.761 52,38.4 v1(52,38)
  Bottom Layer w0.25: v1(32.5,8.2) HDR2.45@32.5,9.7
IO20: HDR2.47 U1.27 | length 81.3
  Bottom Layer w0.2: HDR2.47@33.3,9.7 33.3,8.5 40.8,1 58.5,1 66.9,9.4 66.9,27.3 59.339,34.861 53.739,34.861 50.339,38.261 U1.27@49.41,38.261 ; U1.27@49.4,38.25 U1.27@49.41,38.25
IO21: HDR2.49 U1.29 | length 78.7
  Bottom Layer w0.2: HDR2.49@34.1,9.7 34.1,8.5 41.2,1.4 58.3,1.4 66.5,9.6 66.5,27.1 59.139,34.461 53.339,34.461 50.539,37.261 U1.29@49.41,37.261 ; U1.29@49.4,37.25 U1.29@49.41,37.25
IO22: HDR2.51 U1.30 | length 76.4
  Bottom Layer w0.2: HDR2.51@34.9,9.7 34.9,8.5 41.6,1.8 58.1,1.8 66.1,9.8 66.1,26.9 58.939,34.061 53.139,34.061 50.439,36.761 U1.30@49.41,36.761 ; U1.30@49.4,36.75 U1.30@49.41,36.75
IO23: HDR2.53 U1.31 | length 74
  Bottom Layer w0.2: HDR2.53@35.7,9.7 35.7,8.5 42,2.2 57.9,2.2 65.7,10 65.7,26.7 58.739,33.661 52.939,33.661 50.339,36.261 U1.31@49.41,36.261 ; U1.31@49.4,36.25 U1.31@49.41,36.25
IO24: HDR2.55 U1.33 | length 71.4
  Bottom Layer w0.2: HDR2.55@36.5,9.7 36.5,8.5 42.4,2.6 57.7,2.6 65.3,10.2 65.3,26.5 58.539,33.261 52.739,33.261 50.739,35.261 U1.33@49.41,35.261 ; U1.33@49.4,35.25 U1.33@49.41,35.25
IO25: HDR2.57 U1.34 | length 69.1
  Bottom Layer w0.2: HDR2.57@37.3,9.7 37.3,8.5 42.8,3 57.5,3 64.9,10.4 64.9,26.3 58.339,32.861 52.539,32.861 50.639,34.761 U1.34@49.41,34.761 U1.34@49.448,34.8 ; U1.34@49.4,34.75 U1.34@49.41,34.75
IO26: HDR2.59 U1.35 | length 66.7
  Bottom Layer w0.2: HDR2.59@38.1,9.7 38.1,8.5 43.2,3.4 57.3,3.4 64.5,10.6 64.5,26.1 58.139,32.461 52.339,32.461 50.539,34.261 U1.35@49.41,34.261 ; U1.35@49.4,34.25 U1.35@49.41,34.25
IO27: HDR2.61 U1.36 | length 64.3
  Bottom Layer w0.2: HDR2.61@38.9,9.7 38.9,8.5 43.6,3.8 57.1,3.8 64.1,10.8 64.1,25.9 57.939,32.061 52.139,32.061 50.439,33.761 U1.36@49.41,33.761 ; U1.36@49.4,33.75 U1.36@49.41,33.75
IO28: HDR2.63 U1.37 | length 62.8
  Bottom Layer w0.2: HDR2.63@39.7,9.7 39.7,8.5 44,4.2 56.934,4.2 60.5,7.766 60.5,9.3 60.9,9.7 62.434,9.7 63.7,10.966 63.7,25.7 57.739,31.661 51.939,31.661 50.339,33.261 U1.37@49.41,33.261 ; U1.37@49.4,33.25 U1.37@49.41,33.25
IO29: HDR2.65 U1.41 | length 57.1
  Bottom Layer w0.2: HDR2.65@40.5,9.7 40.5,8.5 44.4,4.6 56.5,4.6 58.6,6.7 58.6,10.9 57.4,12.1 57.4,20.1 60,22.7 60,28.8 57.539,31.261 U1.41@49.41,31.261 ; U1.41@49.4,31.25 U1.41@49.41,31.25
IO30: HDR2.67 U1.42 | length 54.7
  Bottom Layer w0.2: HDR2.67@41.3,9.7 41.3,8.5 44.8,5 56.3,5 58.2,6.9 58.2,10.666 57,11.866 57,16.166 57,20.266 59.6,22.866 59.6,28.6 57.439,30.761 U1.42@49.41,30.761 ; U1.42@49.4,30.75 U1.42@49.41,30.75
IO31: HDR2.69 U1.43 | length 52.3
  Bottom Layer w0.2: HDR2.69@42.1,9.7 42.1,8.5 45.2,5.4 56.1,5.4 57.8,7.1 57.8,10.5 56.6,11.7 56.6,20.431 59.2,23.031 59.2,28.4 57.35,30.25 U1.43@49.4,30.25
IO32: HDR2.71 U1.44 | length 50
  Bottom Layer w0.2: HDR2.71@42.9,9.7 42.9,8.5 45.6,5.8 55.9,5.8 57.4,7.3 57.4,10.266 56.2,11.466 56.2,20.597 58.8,23.197 58.8,28.2 57.25,29.75 U1.44@49.4,29.75
IO33: HDR2.73 U1.45 | length 47.6
  Bottom Layer w0.2: HDR2.73@43.7,9.7 43.7,8.5 46,6.2 55.7,6.2 57,7.5 57,10.1 55.8,11.3 55.8,20.763 58.4,23.363 58.4,28 57.15,29.25 U1.45@49.4,29.25
IO34: HDR2.75 U1.46 | length 45.2
  Bottom Layer w0.2: HDR2.75@44.5,9.7 44.5,8.5 46.4,6.6 55.5,6.6 56.6,7.7 56.6,9.866 55.4,11.066 55.4,20.928 58,23.528 58,27.8 57,28.8 55,28.8 54.961,28.761 U1.46@49.41,28.761
IO35: HDR2.77 U1.47 | length 42.9
  Bottom Layer w0.2: HDR2.77@45.3,9.7 45.3,8.6 46.9,7 55.3,7 56.2,7.9 56.2,9.7 55,10.9 55,21.094 57.6,23.694 57.6,27.6 56.8,28.4 55.169,28.4 55.03,28.261 U1.47@49.41,28.261 ; U1.47@49.4,28.25 U1.47@49.41,28.25
JIOA0: HDR1.3 U1.151 | length 14.9
  Bottom Layer w0.2: HDR1.3@15.7,60.5 15.7,59.4 16.5,58.6 16.5,49.366 17.266,48.6 18.334,48.6 18.484,48.75 U1.151@19.6,48.75
JIOA1: HDR1.5 U1.152 | length 14.2
  Bottom Layer w0.2: HDR1.5@16.5,60.5 16.5,59.2 16.9,58.8 16.9,49.531 17.431,49 18.169,49 18.43,49.261 U1.152@19.61,49.261
JIOA2: HDR1.7 U1.154 | length 11.8
  Bottom Layer w0.2: HDR1.7@17.3,60.5 17.3,51.6 18.639,50.261 U1.154@19.61,50.261
JIOA3: HDR1.9 U1.160 | length 9.5
  Bottom Layer w0.2: HDR1.9@18.1,60.5 18.1,59.2 20.3,57 20.837,57 23.25,54.587 U1.160@23.25,53.4
JIOB0: HDR1.83
JIOB1: HDR1.85
JIOB2: HDR1.87
JIOB3: HDR1.89
KBCLOCK: HDR1.22 U1.135 | length 56
  Bottom Layer w0.2: U1.135@19.6,40.75 18.55,40.75 12.1,47.2 12.1,53.2 4.5,60.8 4.5,66.2 10.5,72.2 19.3,72.2 22.9,68.6 HDR1.22@22.9,67.3
KBDATA: HDR1.24 U1.134 | length 58.4
  Bottom Layer w0.2: U1.134@19.6,40.25 18.45,40.25 11.7,47 11.7,53.034 4.1,60.634 4.1,66.4 10.3,72.6 19.7,72.6 23.7,68.6 HDR1.24@23.7,67.3
LCD_BCKL: HDR2.22 U1.97 | length 8.1
  Top Layer w0.2: v1(22.9,17.934) 23.6,18.634 v1(23.6,20)
  Bottom Layer w0.2: HDR2.22@22.9,16.5 v1(22.9,17.934) ; v1(23.6,20) 25.25,21.65 U1.97@25.25,23.6
LCD_E: HDR2.26 U1.90 | length 8.9
  Bottom Layer w0.2: HDR2.26@24.5,16.5 24.5,18.091 28.76,22.351 U1.90@28.76,23.611
LED0: HDR2.60 U1.63 | length 8.8
  Bottom Layer w0.2: HDR2.60@38.1,16.5 38.1,18.6 42.25,22.75 U1.63@42.25,23.6
LED1: HDR2.62 U1.62 | length 8.7
  Bottom Layer w0.2: HDR2.62@38.9,16.5 38.9,18.8 42.75,22.65 U1.62@42.75,23.6
LED2: HDR2.64 U1.61 | length 8.6
  Bottom Layer w0.2: HDR2.64@39.7,16.5 39.7,19.034 43.25,22.584 U1.61@43.25,23.6
LED3: HDR2.66 U1.59 | length 8.7
  Bottom Layer w0.2: HDR2.66@40.5,16.5 40.5,18.9 44.25,22.65 U1.59@44.25,23.6
LED4: HDR2.68 U1.58 | length 8.5
  Bottom Layer w0.2: HDR2.68@41.3,16.5 41.3,19.134 44.75,22.584 U1.58@44.75,23.6
LED5: HDR2.70 U1.57 | length 8.4
  Bottom Layer w0.2: HDR2.70@42.1,16.5 42.1,19.3 45.25,22.45 U1.57@45.25,23.6
LED6: HDR2.72 U1.49 | length 28.6
  Bottom Layer w0.2: HDR2.72@42.9,16.5 42.9,17.7 43.6,18.4 46.4,18.4 49.4,21.4 50.8,21.4 53.2,23.8 56.3,23.8 56.8,24.3 56.8,27.2 56.4,27.6 55.5,27.6 55.161,27.261 U1.49@49.41,27.261 ; U1.49@49.2,27.3 U1.49@49.41,27.3
LED7: HDR2.74 U1.48 | length 28.7
  Bottom Layer w0.2: HDR2.74@43.7,16.5 43.7,17.6 44.1,18 46.566,18 49.566,21 50.966,21 53.366,23.4 56.5,23.4 57.2,24.1 57.2,27.4 56.6,28 55.334,28 55.096,27.761 U1.48@49.41,27.761 ; U1.48@49.4,27.75 U1.48@49.41,27.75
MOUSECLOCK: HDR1.26 U1.133 | length 60.7
  Bottom Layer w0.2: U1.133@19.6,39.75 18.35,39.75 11.3,46.8 11.3,52.8 3.7,60.4 3.7,66.6 10.1,73 20.1,73 24.5,68.6 HDR1.26@24.5,67.3
MOUSEDATA: HDR1.28 U1.132 | length 63.1
  Bottom Layer w0.2: U1.132@19.6,39.25 18.25,39.25 10.9,46.6 10.9,52.634 3.3,60.234 3.3,66.8 9.9,73.4 20.4,73.4 25.3,68.5 HDR1.28@25.3,67.3
NetLED1_1: LED1.1 R4.1 | length 2.1
  Top Layer w0.2: R4.1@16.45,5.497 LED1.1@18.547,5.497
NetLED1_2: LED1.2 U2.4 | length 2.6
  Top Layer w0.2: U2.4@20.45,7.925 U2.4@20.575,8.05
  Top Layer w0.25: LED1.2@20.45,5.5 U2.4@20.45,7.925
NetLED2_1: LED2.1 R3.2 | length 2.1
  Top Layer w0.2: R3.2@46.45,5.503 LED2.1@48.547,5.503
NEXUS_TCK: HDR1.82 U1.8 | length 39.7
  Bottom Layer w0.2: HDR1.82@46.9,67.3 46.9,68.9 48.3,70.3 55.3,70.3 56,69.6 56,61.3 58.2,59.1 58.2,55.534 53,50.334 53,48.4 52.35,47.75 U1.8@49.4,47.75
NEXUS_TDI: HDR1.84 U1.6 | length 36.1
  Bottom Layer w0.2: HDR1.84@47.7,67.3 47.7,69.1 48.5,69.9 55.1,69.9 55.6,69.4 55.6,61.1 57.8,58.9 57.8,55.7 50.85,48.75 U1.6@49.4,48.75
NEXUS_TDO: HDR1.76 R7.2 | length 39.2
  Top Layer w0.2: R7.2@53.997,49.45 53.997,49.697 v1(54.9,50.6)
  Bottom Layer w0.2: HDR1.76@44.5,67.3 44.5,69.6 46,71.1 55.7,71.1 56.8,70 56.8,61.7 59,59.5 59,55.203 54.9,51.103 v1(54.9,50.6)
NEXUS_TDO#: R7.1 U1.10 | length 6.2
  Top Layer w0.2: R7.1@53.997,47.55 54.1,47.447 v1(54.1,46.3)
  Bottom Layer w0.2: U1.10@49.4,46.75 53.65,46.75 v1(54.1,46.3)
